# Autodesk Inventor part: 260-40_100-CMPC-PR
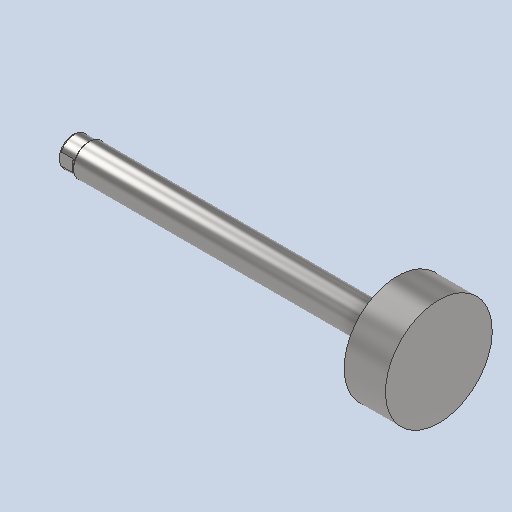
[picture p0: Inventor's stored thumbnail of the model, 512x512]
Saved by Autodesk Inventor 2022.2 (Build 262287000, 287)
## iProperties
Created: 2024-10
Part Number: 260-40_100-CMPC-PR
Material: Acciaio inossidabile
Document SubType Name: Modeling
Designer: 18907419
Density: 8 g/cm^3
Appearance: Default
Author: 18907419
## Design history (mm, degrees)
feature "Solid1"
node "Solido1"
